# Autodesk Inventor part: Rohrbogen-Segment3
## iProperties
Created: 2006-10
Part Number: Rohrbogen-Segment3
Cost Center: 2,98 kg
Material: 1.4301 (X5CrNi18 10)
Document SubType Name: Sheet Metal
Designer: grote
Authority: 373040 mm^3
Manufacturer: Standard
Standards Organization: Custom
Objekthöhe: 10,000 mm
SaveDate: 2006-10-11
SaveTime: 08:21
FileName: Rohrbogen-Segment3
TotalMass: 2,98 kg
TotalVolume: 373040 mm^3
SM_Thickness: 10 mm
SM_Style: NIRO-V80(t =4-10 mm)
SM_Extents: 239,986 mm x 260,224 mm
SM_Square: 62450 mm²
SM_Extents_Width: 239,986 mm
SM_Extents_Length: 260,224 mm
Author: grote
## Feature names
1. Trennen1
2. Trennen2
3. Abgeleiteter Körper1 [Tagging]
4. ExtrusionAbwicklung1
